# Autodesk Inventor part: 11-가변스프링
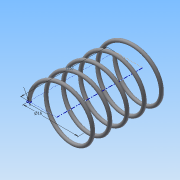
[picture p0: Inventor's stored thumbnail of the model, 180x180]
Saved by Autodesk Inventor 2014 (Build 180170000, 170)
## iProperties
Created: 2015-06
Part Number: 11-가변스프링
Material: 강철, 연강
Document SubType Name: Modeling
Designer: Administrator
Density: 7.86 g/cm^3
Appearance: 강철
Mass: 1.53609 g
Surface Area: 7.89657 cm^2
Volume: 0.195431 cm^3
Author: Administrator
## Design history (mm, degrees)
sketch "스케치1"
  geometry: L1 (0, 0)-(-8, 0); L2 (-8, 0)-(-8, 21.5); L3 (-8, 21.5)-(0, 21.5); L4 (0, 21.5)-(0, 0); C1 r 0.5 at (-8, 0)
  constraints: 8 end point, 2 parallel, 1 centre point, 1 coincident, 1 horizontal, 1 perpendicular
  dimensions: "d0" = 1 diameter of C1; "d1" = 16 diameter of L2 L4; "d2" = 21.5 distance of L1.end L2.end (derived)
feature "코일1" sketch "스케치1" pitch "d3" = 10; turns "d5" = 5; dims "d4" = 21.5 (= d2), "d6" = 0, angle "d7" = 90 deg, angle "d8" = 90 deg, "d9" = 0, "d10" = 0
sketch "스케치2"
  geometry: L1 (8.5, 0)-(7.5, 0) reference; 1 further point
  constraints: 1 horizontal alignment
extrude "돌출1" cut sketch "스케치2" stored distance "d11" = 10; taper "d12" = 0 deg
node "작업 평면1"
sketch "스케치3"
  geometry: L1 (7.5, 0)-(8.5, 0) reference; 1 further point
  constraints: 1 horizontal alignment
extrude "돌출2" cut sketch "스케치3" stored distance "d14" = 10; taper "d15" = 0 deg
node "솔리드1"
node "절단 모서리 투영1"
node "절단 모서리 투영2"
other parameters: "d13" = 21.5 (= d2)
